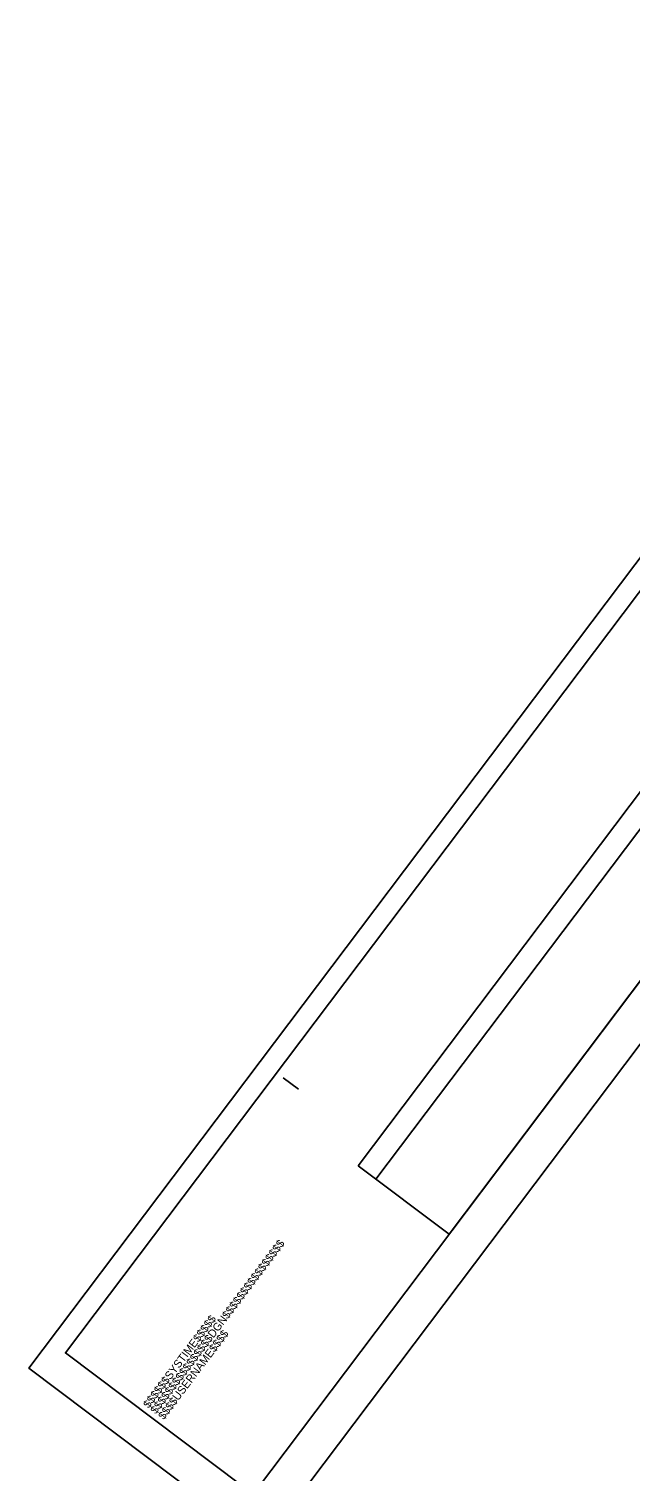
# Model space of a CAD drawing. Extents: x 2296955 to 2298159, y 600182 to 601317.
# Drawn here: x 2296955 to 2297191, y 600750 to 601317 of the extents above; entities that cross this region are included whole.
import ezdxf

# ---------------------------------------------------------------- set-up
doc = ezdxf.new("R2010")
doc.units = 0
for name, color, linetype in [('Exist DTM Drainline Cogo Comment', 7, 'Continuous'), ('Exist DTM Drainline Cogo Elevation', 7, 'Continuous'), ('Exist Roads Curbs Cogo Number', 7, 'Continuous'), ('Exist Roads Curbs Cogo Point CELL', 7, 'Continuous'), ('Exist Roads EOP Cogo Comment', 7, 'Continuous'), ('Exist Roads EOP Other Cogo Elevation', 7, 'Continuous')]:
    doc.layers.add(name, color=color, linetype=linetype)

msp = doc.modelspace()

# ---------------------------------------------------------------- linework, layer by layer
at = {"layer": 'Exist DTM Drainline Cogo Comment'}
msp.add_lwpolyline([(2298148.7, 600700.2), (2297350.15, 601301.97), (2296969.16, 600796.39), (2297767.7, 600194.63)], close=True, dxfattribs=at)
at = {"layer": 'Exist DTM Drainline Cogo Elevation'}
msp.add_line((2297054.86, 600904.64), (2297060.85, 600900.13), dxfattribs=at)
msp.add_lwpolyline([(2298141.78, 600703.5), (2297423.02, 601245.14), (2297043.87, 600742.01), (2297762.63, 600200.36)], close=True, dxfattribs=at)
at = {"layer": 'Exist Roads Curbs Cogo Number'}
msp.add_lwpolyline([(2297423.02, 601245.14), (2297043.89, 600742.01), (2297762.65, 600200.36), (2298069.63, 600607.76), (2297973.78, 600679.99), (2298045.93, 600775.73)], close=True, dxfattribs=at)
at = {"layer": 'Exist Roads Curbs Cogo Point CELL'}
msp.add_lwpolyline([(2298158.96, 600709.34), (2297352.03, 601317.42), (2296954.82, 600790.33), (2297761.75, 600182.24)], close=True, dxfattribs=at)
at = {"layer": 'Exist Roads EOP Cogo Comment'}
msp.add_lwpolyline([(2297425.97, 601224.13), (2297064.9, 600744.96), (2297759.7, 600221.37), (2298062.62, 600623.38), (2297966.76, 600695.61), (2298024.92, 600772.78)], close=True, dxfattribs=at)
at = {"layer": 'Exist Roads EOP Other Cogo Elevation'}
msp.add_line((2297091.26, 600864.71), (2297376.75, 601243.57), dxfattribs=at)
msp.add_lwpolyline([(2297084.33, 600870.03), (2297369.77, 601248.81), (2297405.51, 601221.91), (2297120.07, 600843.12)], close=True, dxfattribs=at)

# ---------------------------------------------------------------- texts
at = {"layer": 'Exist DTM Drainline Cogo Elevation'}
for s, p in [('$$$$$$$$$$$$$$$$DGN$$$$$$$$$$$$$$$$', (2297004.81, 600772.08)), ('$$$$$$SYSTIME$$$$$', (2297001.99, 600774.36)), ('$$$$USERNAME$$$$', (2297007.87, 600769.85))]:
    msp.add_text(s, height=3.15, rotation=52.9991, dxfattribs=at).set_placement(p)

doc.saveas('drawing.dxf')
